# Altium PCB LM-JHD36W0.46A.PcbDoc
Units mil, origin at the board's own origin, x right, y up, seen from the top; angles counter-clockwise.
Board outline 6000 x 4000 mil, 2 copper layers (Top Layer, Bottom Layer); 29 components, 0 nets, 74 pads, 15 vias.
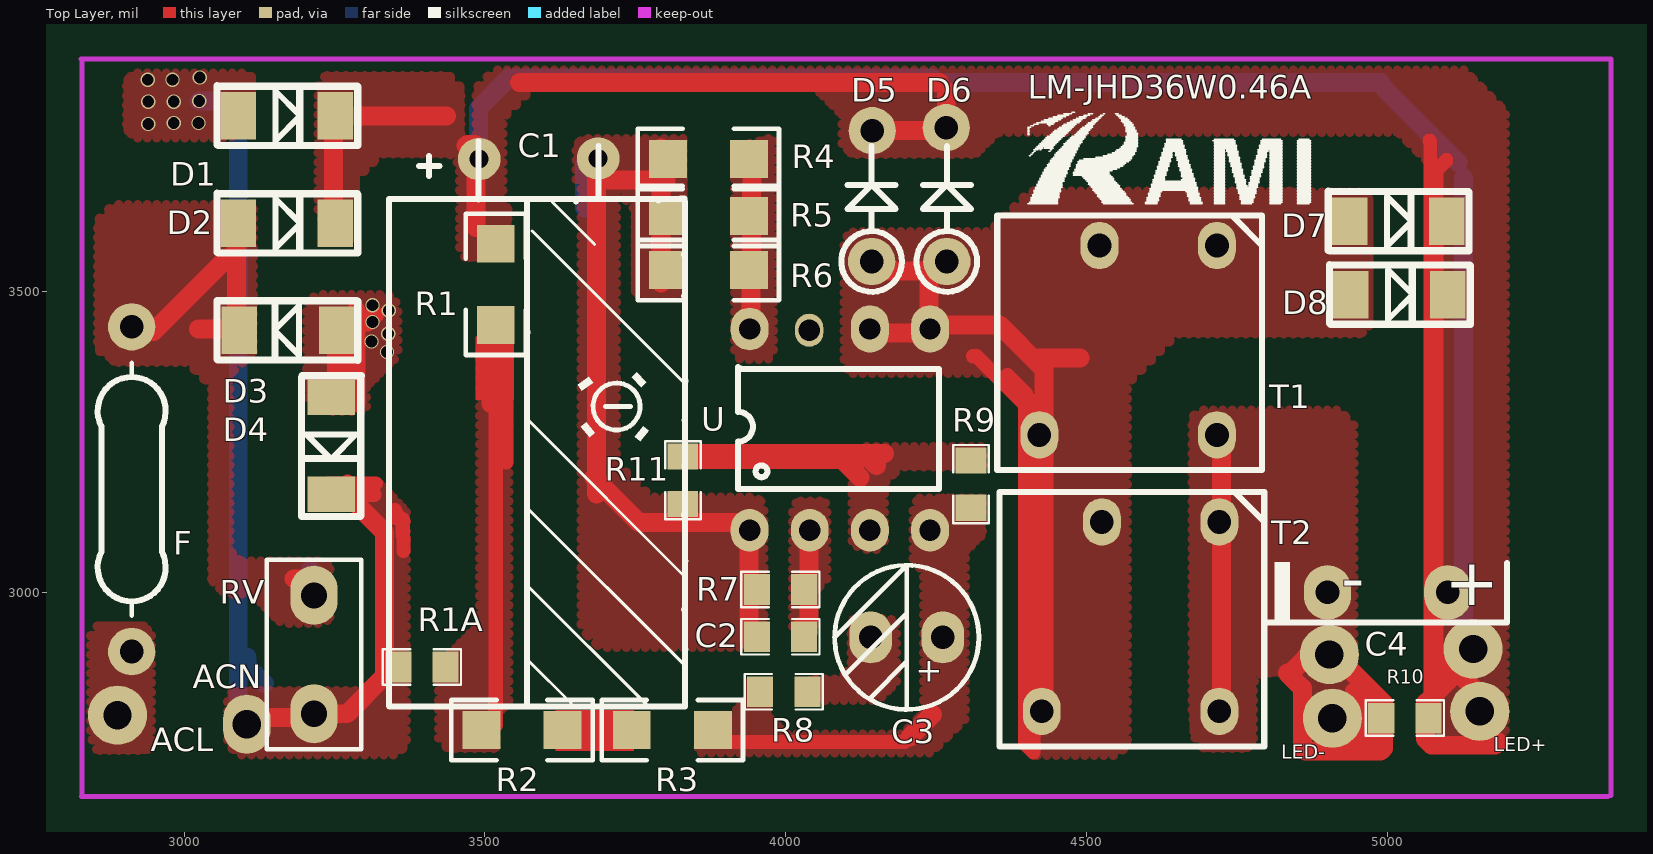
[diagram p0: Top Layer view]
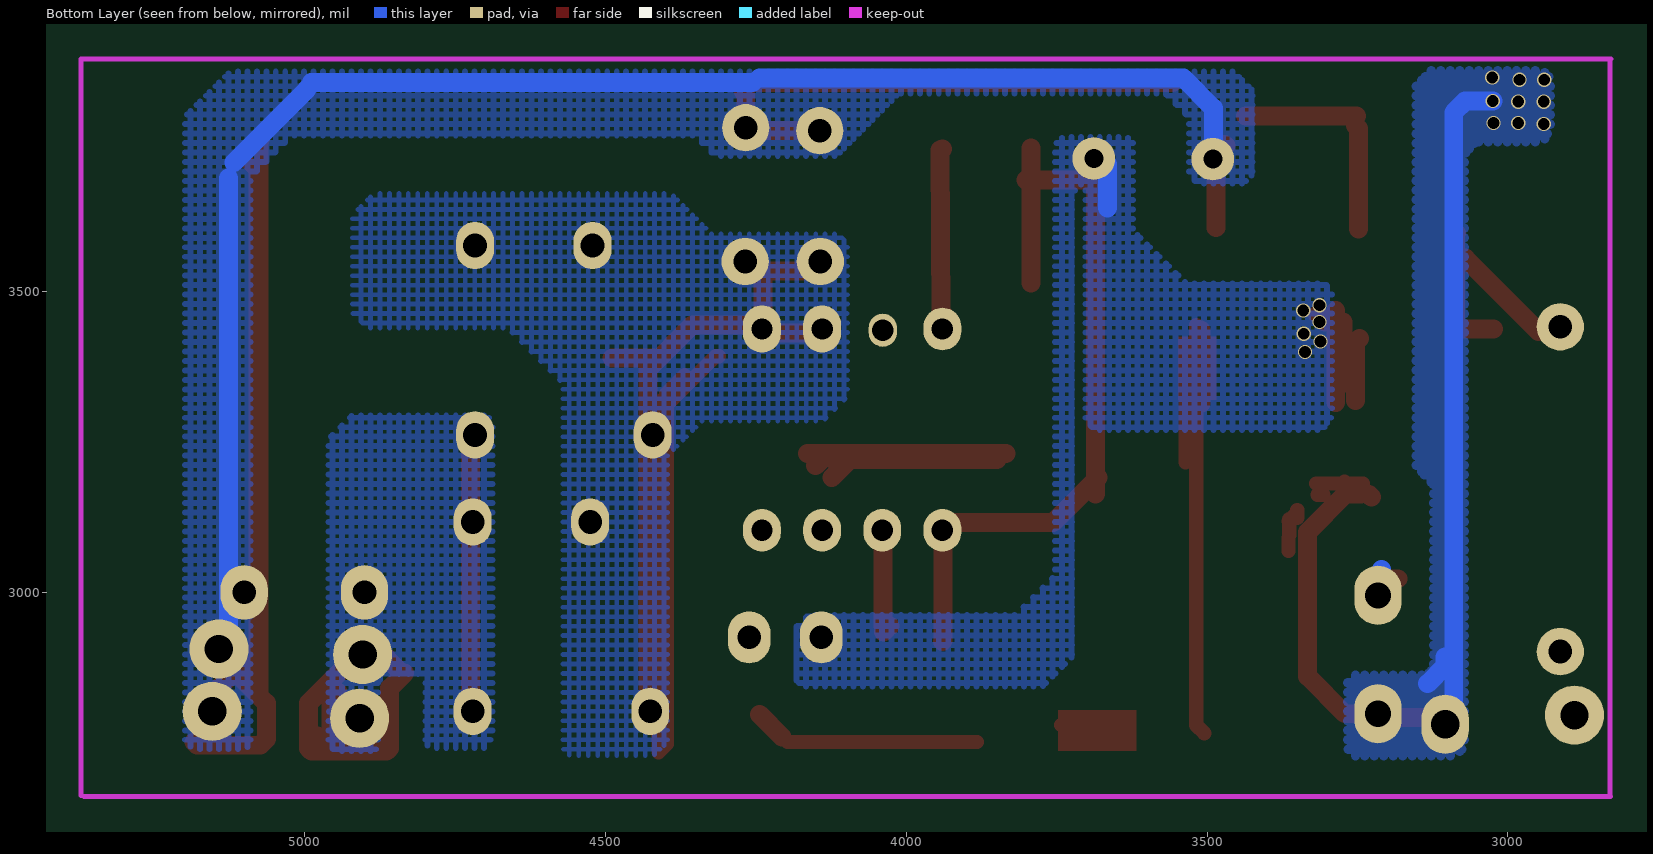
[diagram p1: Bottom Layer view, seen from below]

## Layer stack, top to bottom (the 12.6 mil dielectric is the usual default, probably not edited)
Top Layer: signal copper 1.4
Dielectric: dielectric 12.6, FR-4, Dk 4.8
Bottom Layer: signal copper 1.4

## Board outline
1000,1000 7000,1000 7000,5000 1000,5000

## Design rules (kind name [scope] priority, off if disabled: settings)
Clearance [All] p1: gap=10
ComponentClearance [All] p1: gap=10 collisioncheckmode=3 verticalgap=10
PolygonConnect [All] p1: connectstyle=Relief reliefconductorwidth=10 reliefentries=4 polygonreliefangle="90 Angle"
RoutingVias [All] p1: holewidth=28 width=50 viastyle="Through Hole" minholewidth=28 minwidth=50 maxholewidth=28 maxwidth=50
SolderMaskExpansion [All] p1: expansion=4
TestPointUsage [All] p1: valid=0 allowmultiple=FALSE
Testpoint [All] p1: side=15 testpointundercomponent=TRUE minsize=40 maxsize=100 preferedsize=60 minholesize=0 maxholesize=40 preferedholesize=32 testpointgrid=1 style=1023 order=0123456789
Width [All] p1: maxlimit=10 minlimit=10 preferedwidth=10
18 further rules are at their usual default settings.

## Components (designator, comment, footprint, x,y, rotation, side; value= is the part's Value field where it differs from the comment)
C1 "10uF/400V" "CD  12.5*20   卧式   P5.0（单）" 3589.8,3721.02 r90 top
C2 "Comment" 0805-1 4030.75,2925.75 r270 top
C3 "Comment" CD6 4261.38,2924.76 r180 top
C4 "Comment" "CD10  L" 5100.94,2999.57 r180 top
D1 "Comment" M7 3170.51,3791.89 r270 top
D2 "Comment" M7 3170.51,3613.08 r270 top
D3 "Comment" M7 3244.33,3243.66 r180 top
D4 "Comment" M7 3172.48,3435.26 r90 top
D5 "Comment" IN4007L#1 4142.95,3577.32 r90 top
D6 "Comment" IN4007L#2 4267.95,3577.32 r90 top
D7 "Comment" M7 5018.27,3616.69 r270 top
D8 "Comment" M7 5020.23,3494.65 r270 top
F "Comment" 1/2W 2912.64,2901.14 r90 top
R1 "Comment" 1206 3517.95,3579.29 r270 top
R1A "Comment" 0805-1 3355.94,2875.55 r90 top
R2 "Comment" 1206 3494.05,2770.43 r0 top
R3 "Comment" 1206 3744.05,2770.43 r0 top
R4 "Comment" 1206 3804.05,3720.43 r0 top
R5 "Comment" 1206 3804.05,3625.43 r0 top
R6 "Comment" 1206 3804.05,3535.43 r0 top
R7 "Comment" 0805-1 4030.75,3004.49 r270 top
R8 "Comment" 0805-1 4036.05,2834.41 r270 top
R9 "Comment" 0805-1 4308.3,3219.06 r0 top
R10 "Comment" 0805-1 5069.05,2790.43 r270 top
R11 "Comment" 0805-1 3829.05,3225.43 r0 top
RV "Comment" MOV7D 3215.78,2797.8 r0 top
T1 "Comment" EE10L 4717.08,3576.33 r180 top
T2 "Comment" EE10L 4721.02,3116.69 r180 top
U "Comment" DIP-8 3940.12,3102.4 r90 top

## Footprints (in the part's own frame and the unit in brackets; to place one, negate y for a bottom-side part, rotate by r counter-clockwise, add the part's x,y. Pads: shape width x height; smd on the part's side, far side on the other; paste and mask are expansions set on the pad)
1/2W [mm]
  round 2 hole 1: 1(0,0) 2(13.716,0)
  silkscreen extent 1.52,-1.44 12.19,1.44
0805-1 [mm]
  rect 1.3x1.1 smd: 1(0,0) 2(0,-2)
  silkscreen extent -0.75,-2.65 0.75,0.65
1206 [mm]
  rect 1.6x1.6 smd: 1(0,0) 2(3.429,0)
  silkscreen extent -1.27,-1.27 4.7,1.27
CD6 [mm]
  oval 1.8x2.2 hole 1: 1(0,0) 2(3.048,0)
  silkscreen extent -1.52,-3.05 4.57,3.05
"CD10  L" [mm]
  oval 2x2.3 hole 1: 1(0,0) 2(5.08,0)
  silkscreen extent -2.5,-1.27 7.75,1.28
"CD  12.5*20   卧式   P5.0（单）" [mm]
  round 1.8 hole 0.8: 1(-0.025,2.525) 2(0,-2.5)
  silkscreen extent -23.15,-6.2 0.71,6.34
DIP-8 [mm]
  oval 1.8x1.6 hole 0.9: 1-VDD(0.012,0.002) 2-NC(0.012,-2.538) 3-DIM(0.012,-5.078) 4-CS(0.012,-7.618) 7-GND(8.512,0.002)
  oval 2x1.6 hole 0.9: 5-Drain(8.512,-7.618) 6-Drain(8.512,-5.078)
  silkscreen extent 1.75,-8 6.9,0.5
EE10L [mm]
  oval 1.6x2 hole 1: 1(0,0) 3(4.96,0) 5(7.5,8) 8(0,8)
  silkscreen extent -1.9,-1.27 9.28,9.48
IN4007L#1 [mm]
  round 2 hole 1: 1(-0.7,0) 2(4.825,-0.025)
  silkscreen extent -1.98,-1.28 4.18,1.28
IN4007L#2 [mm]
  round 2 hole 1: 1(-0.7,0) 2(4.95,0.025)
  silkscreen extent -1.98,-1.28 4.18,1.28
M7 [mm]
  rect 2x1.5 smd: 1(0,-2.05) 2(0,2.05)
  silkscreen extent -1.27,-2.95 1.25,3
MOV7D [mm]
  oval 2x2.5 hole 1.1: 1(0,0) 2(0,5)
  silkscreen extent -2,-1.5 2,6.5

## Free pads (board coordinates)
  oval 47.24x55.12 hole 35.43: 0(4039.05,3435.43)
  round 98.43 hole 47.24: 0(4909.05,2790.43) 1(5154.05,2801.73) 2(4904.05,2896.22) 3(5142.94,2905.43) 4(2889.05,2795.43)
  oval 78.74x98.43 hole 47.24: 5(3104.05,2780.43)

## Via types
v1: diameter 23.62, hole 19.68, Top Layer to Bottom Layer, 15 vias

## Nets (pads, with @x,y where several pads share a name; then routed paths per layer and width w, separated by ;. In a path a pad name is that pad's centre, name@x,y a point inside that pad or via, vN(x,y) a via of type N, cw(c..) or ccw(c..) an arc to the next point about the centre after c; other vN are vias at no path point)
pads on no net: C1.1 C1.2 C2.1 C2.2 C3.1 C3.2 C4.1 C4.2 D1.1 D1.2 D2.1 D2.2 D3.1 D3.2 D4.1 D4.2 D5.1 D5.2 D6.1 D6.2 D7.1 D7.2 D8.1 D8.2 F.1 F.2 R1.1 R1.2 R1A.1 R1A.2 R2.1 R2.2 R3.1 R3.2 R4.1 R4.2 R5.1 R5.2 R6.1 R6.2 R7.1 R7.2 R8.1 R8.2 R9.1 R9.2 R10.1 R10.2 R11.1 R11.2 RV.1 RV.2 T1.1 T1.3 T1.5 T1.8 T2.1 T2.3 T2.5 T2.8 U.1-VDD U.2-NC U.3-DIM U.4-CS U.5-Drain U.6-Drain U.7-GND
copper on no net: | length 16670.7
  Top Layer w23.62: 3240.71,3180.67 3318.46,3180.67 ; 3261.38,3174.76 3262.36,3174.76 3271.22,3183.62 ; 3306.65,3161.97 3316.49,3161.97 ; 3349.96,3123.58 3349.96,3136.38 ; 3355.86,3126.54 3364.72,3117.68 ; 3363.42,3095.04 3363.42,3121.29 ; 3364.72,3068.46 3364.72,3090.12 ; 3504.49,2765.32 3517.95,2778.78 3517.95,3444.29 ; 3519.25,3336.18 3535.98,3352.91 3535.98,3216.1 ; 3641.3,2777.13 3643.27,2779.09 3742.67,2779.09 ; 3882.44,2750.55 4197.4,2750.55 4243.39,2796.54 ; 4311.57,3392.28 4317.48,3392.28 4398.19,3311.57 4398.19,2747.6 4411.97,2733.82 4411.97,2761.38 4412.95,2762.36 4412.95,3312.56 4399.17,3326.34 4399.17,3330.28 4368.66,3360.79 ; 4941.49,2836.18 4960.19,2817.48 4960.19,2761.38 ; 5070.43,3750.55 5072.4,3748.58 5072.4,2818.46 ; 5082.24,2828.31 5082.24,3701.34 5098.97,3718.07
  Top Layer w31.5: 2949.05,3433.62 3070.61,3555.18 ; 3023.86,3437.56 3077.01,3437.56 ; 3084.88,3597.01 3086.85,3595.04 3086.85,3451.34 ; 3104.56,2788.94 3107.52,2791.89 3199.05,2791.89 ; 3182.32,3022.2 3193.15,3022.2 ; 3207.91,2797.8 3270.9,2797.8 3332.91,2859.8 3332.91,3099.96 3269.92,3162.95 3244.33,3162.95 ; 3226.61,3158.03 3230.55,3161.97 ; 3246.3,3421.81 3253.19,3414.92 3253.19,3318.46 ; 3248.27,3603.9 3248.27,3771.22 3253.19,3776.14 ; 3251.22,3791.89 3436.26,3791.89 ; 3273.86,3347.01 3273.86,3449.37 3304.37,3449.37 3316.18,3461.18 ; 3285.98,3315.51 3285.98,3468.07 ; 3468.74,3742.68 3470.71,3744.65 3483.5,3744.65 ; 3485.47,3605.87 3485.47,3736.77 ; 3510.08,3313.54 3510.08,3435.59 ; 3557.32,3847.01 4256.14,3847.01 ; 3681.34,3190.51 3756.14,3115.71 3926.41,3115.71 ; 3685.27,3162.95 3685.27,3697.4 ; 3694.13,3685.59 3801.41,3685.59 ; 3792.56,3514.25 3792.56,3738.66 ; 3834.05,3230.43 3844.05,3230.43 4164.05,3230.43 ; 3849.05,3220.43 4120.82,3220.43 ; 3928.38,3451.34 3942.16,3465.12 ; 3939.14,3117.15 3939.14,2918.93 3940.19,2917.87 ; 3939.52,3737.09 3943.95,3735.04 3942.16,3457.24 ; 4027.32,2943.94 4037.64,2933.62 ; 4039.13,2943.94 4039.13,3117.17 ; 4059.05,3225.43 4089.05,3225.43 4124.05,3190.43 ; 4132.12,3540.91 4139.01,3534.02 4233.5,3534.02 4238.42,3529.09 4238.42,3459.21 ; 4140.82,3220.43 4150.82,3210.43 ; 4143.93,3767.28 4262.04,3767.28 4266.97,3772.2 4266.97,3827.32 4270.9,3831.26 ; 4150.82,3430.67 4233.24,3430.67 4247.02,3444.45 4355.55,3444.45 4429.37,3370.63 4429.37,2812.56 ; 4206.93,2759.41 4244.06,2796.54 ; 4421.49,3389.33 4489.41,3389.33 ; 4723.66,2822.4 4729.56,2816.5 ; 4724.64,2808.62 4724.64,3265.32 ; 4924.05,2740.43 4919.05,2735.43 4864.05,2735.43 4859.05,2740.43 4859.05,2840.43 4834.05,2865.43 4839.05,2865.43 4884.05,2910.43 4899.05,2910.43 4994.05,2815.43 4994.05,2740.43 4989.05,2735.43 4924.05,2735.43 4939.05,2750.43 4979.05,2750.43 4979.05,2760.43 ; 5144.05,2750.43 5144.05,2840.43 5104.05,2880.43 5104.05,2855.43 5064.05,2815.43 5064.05,2755.43 5074.05,2745.43 5179.05,2745.43 5184.05,2750.43
  Bottom Layer w31.5: v1(3024.84,3816.5) 3071.1,3816.5 3089.8,3797.8 3089.8,3221.02 3089.8,2818.46 ; 3104.56,2892.28 3104.56,2876.54 3133.11,2847.99 ; 3209.88,3023.19 3209.88,3037.95 ; 3489.41,3703.31 3489.41,3804.69 3539.6,3854.88 4244.33,3854.88 ; 3665.59,3638.35 3665.59,3712.17 ; 4256.14,3847.01 4989.41,3847.01 ; 4996.3,3836.18 5118.34,3714.13 ; 5127.2,2892.28 5127.2,3688.54
  other v1: 3337.16,3399.17 3311.57,3416.89 3339.13,3429.69 3313.23,3449.37 3340.12,3468.07 3313.23,3476.93 2940.19,3778.11 2982.52,3780.08 3023.86,3780.08 2940.19,3815.51 2982.52,3815.51 2939.21,3851.93 2980.55,3851.93 3025.82,3855.87

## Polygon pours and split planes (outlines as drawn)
no net on Top Layer "Top Layer-No Net 1" (hatched 90Degree grid 15.75 track 15.75, pour order 1003): 3860.78,2794.84 3861.77,2793.86 3895.23,2793.86 3908.03,2793.86 3940.51,2826.34 3945.43,2821.42 3960.19,2821.42 3960.19,2797.8 3984.8,2773.19 3994.64,2763.35 4047.79,2763.35 4193.46,2763.35 4229.88,2799.76 4229.88,2920.83 4229.88,3034.02 4219.05,3044.84 4213.15,3050.75 4212.16,3051.73 4212.16,3139.33 4212.16,3145.24 4222.99,3156.06 4261.06,3156.06 4273.19,3156.06 4326.34,3102.91 4298.78,3075.35 4298.78,2955.28 4298.78,2789.92 4263.34,2754.49 4241.69,2732.83 4216.1,2732.83 3858.82,2732.83 3855.86,2735.79 3854.88,2736.77 3854.88,2745.63
no net on Top Layer "Top Layer-No Net 1" (hatched 90Degree grid 15.75 track 15.75, pour order 1000): 3203.3,3325.35 3203.3,3478.9 3219.05,3494.65 3339.13,3494.65 3354.88,3478.9 3354.88,3393.27 3302.71,3341.1 3302.71,3304.69 3298.78,3300.75 3245.63,3300.75
no net on Top Layer "Top Layer-No Net 1" (hatched 90Degree grid 15.75 track 15.75, pour order 1001): 3874.05,2765.43 3904.05,2765.43 3934.05,2795.43 3939.05,2800.43 3939.05,2850.43 3964.05,2850.43 3969.05,2845.43 3969.05,2810.43 3969.05,2795.43 3999.05,2765.43 3994.05,2760.43 3944.05,2760.43
no net on Top Layer "Top Layer-No Net 1" (hatched 90Degree grid 15.75 track 15.75, pour order 1000): 4039.05,2855.43 4089.05,2855.43 4109.05,2875.43 4109.05,2945.43 4109.05,2950.43 4114.05,2955.43 4164.05,2955.43 4174.05,2955.43 4179.05,2950.43 4184.05,2945.43 4184.05,2870.43 4184.05,2850.43 4164.05,2830.43 4154.05,2820.43 4034.05,2820.43
no net on Top Layer "Top Layer-No Net" (hatched 90Degree grid 15.75 track 15.75, pour order 1000): 4412.64,2728.9 4551.41,2728.9 4568.15,2745.63 4568.15,3346.02 4670.5,3448.38 4437.24,3448.38 4437.24,3333.23
no net on Top Layer "Top Layer-No Net 1" (hatched 90Degree grid 15.75 track 15.75, pour order 1001): 3915.59,3714.81 3915.59,3395.86 3924.45,3387.36 3970.71,3387.36 3979.56,3395.86 3979.56,3749.73 3975.63,3753.5 3960.86,3753.5
no net on Top Layer "Top Layer-No Net 2" (hatched 90Degree grid 15.75 track 15.75, pour order 1002): 3651.81,3678.76 3651.81,3742.83 3662.64,3753.5 3829.96,3753.5 3829.96,3492.39 3758.11,3492.39 3750.23,3500.15 3750.23,3636.05 3688.23,3697.2 3688.23,3700.12 3718.74,3670.02 3718.74,3214.77 3765.98,3168.18 3776.81,3157.5 3952.01,3157.5 3963.82,3145.85 3963.82,2908.03 3691.18,2908.03 3659.68,2939.09 3659.68,3726.32
no net on Top Layer "Top Layer-No Net 3" (hatched 90Degree grid 15.75 track 15.75, pour order 1003): 4012.04,2936.57 4012.04,3142.28 4020.9,3151.14 4063.23,3151.14 4068.15,3146.22 4068.15,3021.22 4039.13,2992.2 4039.13,2933.62
no net on Top Layer "Top Layer-No Net 7" (hatched 90Degree grid 15.75 track 15.75, pour order 1007): 3222.67,3630.47 3222.67,3846.02 3235.47,3858.82 3440.19,3858.82 3459.88,3839.13 3459.88,3732.83 3514.01,3732.83 3514.01,3661.97 3537.64,3638.35 3537.64,3556.65 3467.75,3556.65 3457.91,3566.5 3457.91,3711.18 3440.19,3728.9 3327.99,3728.9 3284.68,3685.59 3284.68,3593.07 3274.84,3583.23 3251.22,3583.23
no net on Top Layer "Top Layer-No Net 8" (hatched 90Degree grid 15.75 track 15.75, pour order 1008): 3485.47,3718.07 3485.47,3838.15 3515,3867.68 5128.19,3867.68 5196.1,3799.76 5196.1,2749.57 5186.26,2739.72 5096.69,2739.72 5087.83,2748.58 5087.83,3695.43 5018.93,3764.33 4351.61,3764.33 4315.19,3727.91 4111.45,3727.91 4093.74,3745.63 4093.74,3793.86 4047.48,3840.12 3581.93,3840.12 3529.76,3787.95 3529.76,3598.98 3516.97,3598.98 3496.3,3619.65
no net on Top Layer "Top Layer-No Net 9" (hatched 90Degree grid 15.75 track 15.75, pour order 1009): 4676.41,2796.81 4676.41,3290.91 4687.35,3302.72 4920.74,3302.72 4944.45,3277.13 4944.45,2740.71 4933.51,2728.9 4870.6,2728.9 4861.48,2738.74 4861.48,2853.9 4850.54,2865.71 4792.2,2865.71 4777.61,2849.96 4777.61,2751.54 4767.58,2740.71 4695.56,2740.71 4680.97,2756.46
no net on Top Layer "Top Layer-No Net 10" (hatched 90Degree grid 15.75 track 15.75, pour order 1010): 3077.99,3755.47 2918.54,3755.47 2904.76,3769.25 2904.76,3850.94 2916.57,3862.76 3105.55,3862.76 3111.45,3856.85 3111.45,3797.8
no net on Top Layer "Top Layer-No Net 11" (hatched 90Degree grid 15.75 track 15.75, pour order 1011): 3072.08,2746.61 3072.08,2826.34 3081.46,2836.18 3299.94,2836.18 3327.13,2864.72 3327.13,3095.04 3263.37,3161.97 3243.68,3182.64 3323.38,3182.64 3369.33,3134.41 3369.33,2746.61 3353.39,2729.88 3089.9,2729.88 3082.4,2737.76
no net on Top Layer "Top Layer-No Net 12" (hatched 90Degree grid 15.75 track 15.75, pour order 1012): 2844.72,2765.32 2844.72,2932.64 2855.55,2943.46 2932.32,2943.46 2945.12,2930.67 2945.12,2745.63 2936.26,2736.77 2856.53,2736.77 2848.66,2744.65
no net on Top Layer "Top Layer-No Net 13" (hatched 90Degree grid 15.75 track 15.75, pour order 1013): 2856.53,3401.14 2856.53,3618.66 2882.12,3644.25 3114.41,3644.25 3114.41,3400.16 3076.02,3361.77 3076.02,3069.45 3093.74,3051.73 3234.49,3051.73 3242.36,3043.86 3242.36,2958.23 3232.52,2948.39 3161.65,2948.39 3112.44,2997.6 3068.15,2997.6 3045.51,3020.24 3045.51,3342.09 3005.15,3382.44 2884.09,3382.44 2867.36,3399.17
no net on Top Layer "Top Layer-No Net 14" (hatched 90Degree grid 15.75 track 15.75, pour order 1014): 4808.3,3603.9 4808.3,3664.92 4958.9,3664.92 4969.72,3654.09 4969.72,3442.48 4956.93,3429.69 4595.71,3429.69 4595.71,3507.44
no net on Top Layer "Top Layer-No Net 15" (hatched 90Degree grid 15.75 track 15.75, pour order 1015): 4418.22,2754.48 4418.22,3323.39 4378.28,3363.74 4110.37,3363.74 4097.71,3376.54 4097.71,3587.17 4109.4,3598.98 4339.27,3598.98 4406.47,3666.89 4850.63,3666.89 4850.63,3526.14 4713.29,3526.14 4604.2,3415.9 4541.86,3352.91 4541.86,2792.87
no net on Top Layer "Top Layer-No Net 16" (hatched 90Degree grid 15.75 track 15.75, pour order 1016): 4110.47,3085.2 4110.47,3223.98 4128.19,3241.69 4327.99,3241.69 4327.99,3208.23 4191.18,3208.23 4173.46,3190.51 4163.62,3180.67 4163.62,3079.29 4155.75,3071.42 4124.25,3071.42
no net on Top Layer "Top Layer-No Net 17" (hatched 90Degree grid 15.75 track 15.75, pour order 1017): 4243.34,3138.35 4261.06,3156.06 4327.01,3156.06 4327.01,3096.02 4281.73,3050.75 4255.15,3077.32
no net on Top Layer "Top Layer-No Net 1" (hatched 90Degree grid 15.75 track 15.75, pour order 1000): 3491.69,3409.02 3491.69,2947.4 3422.79,2878.5 3422.79,2755.47 3437.56,2740.71 3518.27,2740.71 3518.27,2795.83 3539.92,2817.48 3539.92,3375.55
no net on Bottom Layer "Bottom Layer-No Net" (hatched 90Degree grid 15.75 track 15.75, pour order 1018): 2929.37,3774.41 2929.37,3853.93 2941.13,3866.69 3128.44,3866.69 3151.97,3841.17 3151.97,3209.93 3123.92,3179.5 3123.92,2873.21 3134.77,2861.43 3254.22,2861.43 3265.98,2848.66 3265.98,2739.69 3255.12,2727.91 3086.82,2727.91 3072.34,2743.62 3072.34,3728.27 3053.34,3748.89 2940.23,3748.89
no net on Bottom Layer "Bottom Layer-No Net 1" (hatched 90Degree grid 15.75 track 7.87, pour order 1019): 4396.89,2750.55 4396.89,3226.93 4339.8,3284.02 4139.01,3284.02 4110.47,3312.56 4097.67,3325.35 4097.67,3580.28 4113.42,3596.02 4324.05,3596.02 4390.98,3662.95 4885.08,3662.95 4921.49,3626.54 4921.49,3464.13 4895.9,3438.54 4662.64,3438.54 4595.71,3371.61 4571.1,3347.01 4571.1,2739.72 4559.29,2727.91 4420.51,2727.91 4410.67,2737.76
no net on Bottom Layer "Bottom Layer-No Net 2" (hatched 90Degree grid 15.75 track 9.84, pour order 1020): 3424.45,3694.45 3424.45,3834.21 3444.13,3853.9 3455.94,3865.71 5124.25,3865.71 5199.05,3790.91 5199.05,2752.52 5185.27,2738.74 5099.64,2738.74 5090.78,2747.6 5090.78,3689.53 5020.9,3759.41 4352.6,3759.41 4318.15,3724.96 4116.38,3724.96 4012.04,3829.29 3570.12,3829.29 3540.59,3799.76 3529.76,3788.94 3529.76,3693.46 3515.98,3679.69 3439.21,3679.69
no net on Bottom Layer "Bottom Layer-No Net 3" (hatched 90Degree grid 15.75 track 9.84, pour order 1021): 4688.23,2765.32 4688.23,3284.02 4698.07,3293.86 4921.49,3293.86 4960.86,3254.49 4960.86,2746.61 4950.04,2735.79 4885.08,2735.79 4878.19,2742.68 4878.19,2850.94 4865.39,2863.74 4811.26,2863.74 4799.45,2851.93 4799.45,2747.6 4792.56,2740.71 4700.04,2740.71 4693.15,2747.6
no net on Bottom Layer "Bottom Layer-No Net 4" (hatched 90Degree grid 15.75 track 9.84, pour order 1022): 3292.56,3291.89 3292.56,3501.54 3304.37,3513.35 3534.68,3513.35 3623.27,3601.93 3623.27,3747.6 3632.12,3756.46 3740.39,3756.46 3753.19,3743.66 3753.19,3027.13 3818.15,2962.17 4162.64,2962.17 4182.32,2942.48 4182.32,2852.91 4172.48,2843.07 3773.86,2843.07 3724.64,2892.28 3724.64,3662.95 3691.18,3696.42 3702.01,3685.59 3702.01,3285 3686.26,3269.25 3308.3,3269.25

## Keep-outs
Keep-Out Layer:
  lines w7.87: 2828.3,3886.46 5372.32,3886.46 5372.32,2661.97 ; 2829.29,2660 5367.67,2660 ; 2830,2660 2830,3885.47

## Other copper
Top Layer:
  rectangle: 3484.49,3319.45 3548.46,3424.76
  rectangle: 3617.67,2735.79 3747.6,2803.7

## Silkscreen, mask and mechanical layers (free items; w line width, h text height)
Top Overlay:
  drawing of 438 lines, arcs and shapes, not listed
  text "LM-JHD36W0.46A" at 4402.79,3820.43 h39.37
  text "ACN" at 3014.05,2840.43 h39.37
  text "ACL" at 2944.05,2735.43 h39.37
  text "LED+" at 5177.4,2727.91 h39.37
  text "LED-" at 4824.05,2715.43 h39.37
